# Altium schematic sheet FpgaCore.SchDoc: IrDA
size A4; Organization: Microprocessor-Design Pty Ltd; Address1: 18/110 Caroline Street; Address2: South Yarra; Address3: VIC 3141; Address4: Australia; DocumentNumber: 1; SheetNumber: 1; SheetTotal: 3
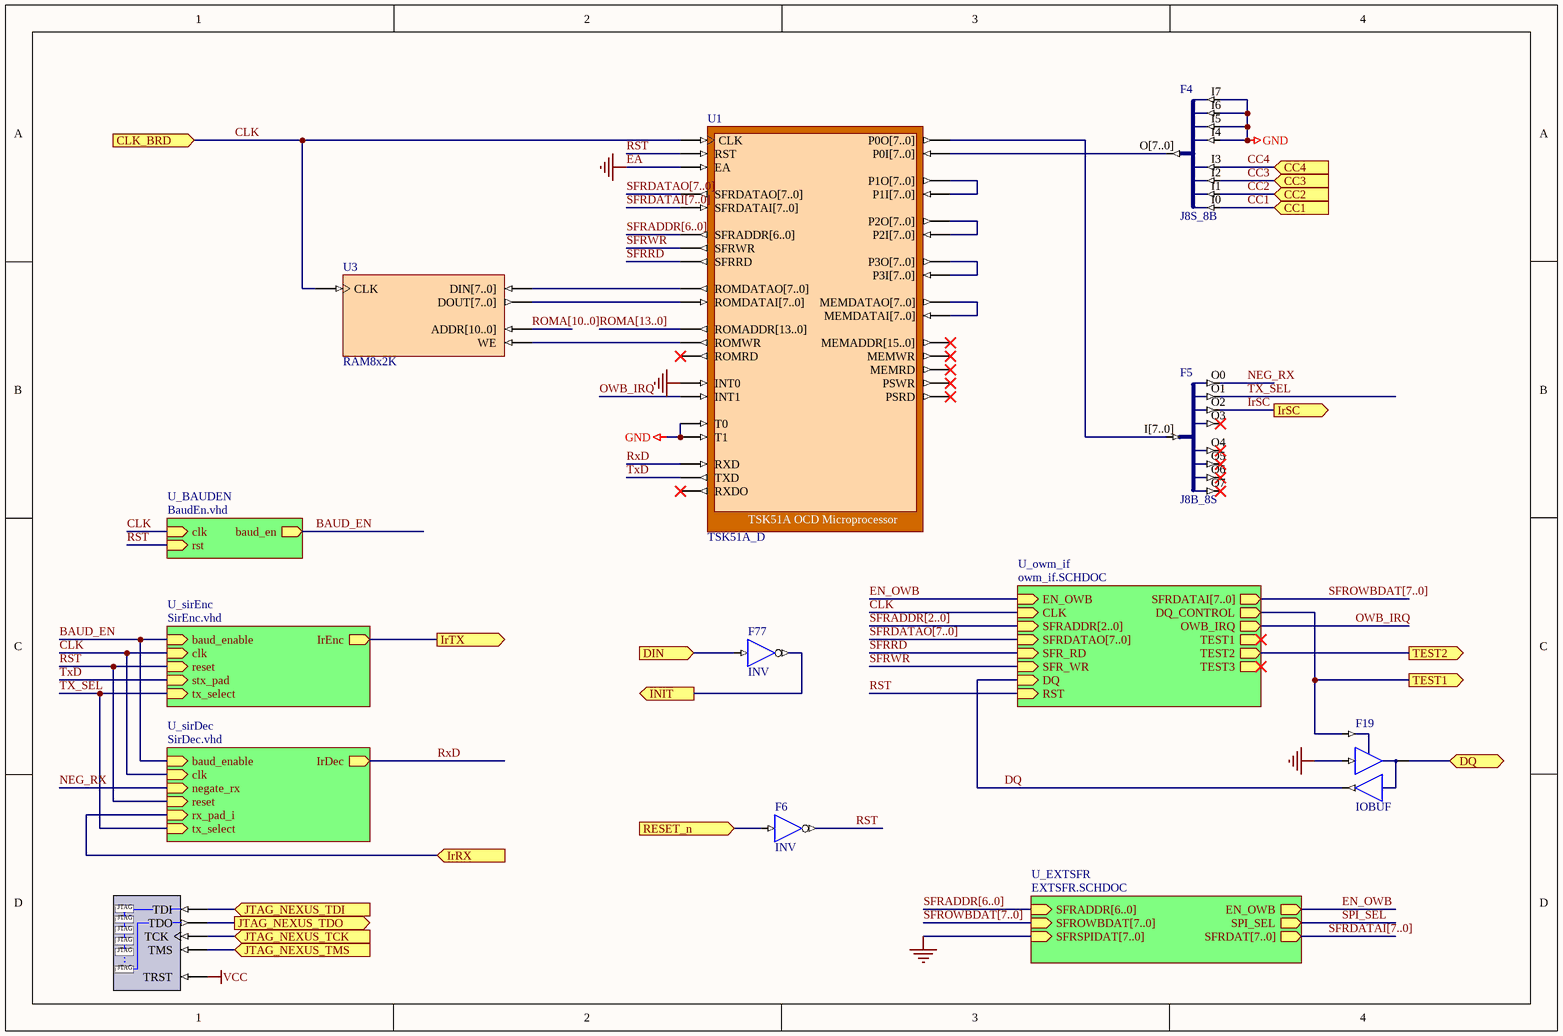
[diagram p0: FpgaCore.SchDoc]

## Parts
F4  J8S_8B
F5  J8B_8S
F6  INV
F19  IOBUF
F77  INV
NEXUS_JTAG_PORT  NEXUS_JTAG_PORT  (value not drawn)
U1  TSK51A_D
U3  RAM8x2K

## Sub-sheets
U_BAUDEN = BaudEn.vhd: baud_en (out), clk (in), rst (in)  | VHDLENTITY: BAUDEN
U_EXTSFR = EXTSFR.SCHDOC: SFRADDR[6..0] (in), EN_OWB (out), SPI_SEL (out), SFROWBDAT[7..0] (in), SFRSPIDAT[7..0] (in), SFRDAT[7..0] (out)
U_owm_if = owm_if.SCHDOC: EN_OWB (in), CLK (in), SFRADDR[2..0] (in), SFRDATAO[7..0] (in), SFRDATAI[7..0] (out), DQ_CONTROL (out), OWB_IRQ (out), SFR_RD (in), SFR_WR (in), DQ (in), RST (in), TEST1 (out), TEST2 (out), TEST3 (out)
U_sirDec = SirDec.vhd: baud_enable (in), clk (in), IrDec (out), negate_rx (in), reset (in), rx_pad_i (in), tx_select (in)  | VHDLENTITY: sirDec
U_sirEnc = SirEnc.vhd: baud_enable (in), clk (in), IrEnc (out), reset (in), stx_pad (in), tx_select (in)  | VHDLENTITY: sirEnc

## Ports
CC1 (in), CC2 (in), CC3 (in), CC4 (in), CLK_BRD (in), DIN (in), DQ (bidir), INIT (out), IrRX (in), IrSC (out), IrTX (out), JTAG_NEXUS_TCK (in), JTAG_NEXUS_TDI (in), JTAG_NEXUS_TDO (out), JTAG_NEXUS_TMS (in), RESET_n (in), TEST1 (out), TEST2 (out)

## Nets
EA: F4.I4 F4.I5 F4.I6 F4.I7 F19.I U1.EA U1.INT0 U1.T0 U1.T1  [also labelled GND]
VCC: NEXUS_JTAG_PORT.TRST
BAUD_EN: sheet U_sirDec/baud_enable, sheet U_sirEnc/baud_enable, sheet U_BAUDEN/baud_en
CC1: F4.I0 ; port CC1
CC2: F4.I1 ; port CC2
CC3: F4.I2 ; port CC3
CC4: F4.I3 ; port CC4
CLK: U1.CLK U3.CLK ; port CLK_BRD, sheet U_sirDec/clk, sheet U_sirEnc/clk, sheet U_BAUDEN/clk, sheet U_owm_if/CLK
DIN: F77.I ; port DIN
DQ: F19.O ; sheet U_owm_if/DQ
DQ: F19.IO ; port DQ  [a separate net that carries the same name]
EN_OWB: sheet U_EXTSFR/EN_OWB, sheet U_owm_if/EN_OWB
INIT: F77.O ; port INIT
IrRX: port IrRX, sheet U_sirDec/rx_pad_i
IrSC: F5.O2 ; port IrSC
IrTX: port IrTX, sheet U_sirEnc/IrEnc
JTAG_NEXUS_TCK: NEXUS_JTAG_PORT.TCK ; port JTAG_NEXUS_TCK
JTAG_NEXUS_TDI: NEXUS_JTAG_PORT.TDI ; port JTAG_NEXUS_TDI
JTAG_NEXUS_TDO: NEXUS_JTAG_PORT.TDO ; port JTAG_NEXUS_TDO
JTAG_NEXUS_TMS: NEXUS_JTAG_PORT.TMS ; port JTAG_NEXUS_TMS
NEG_RX: F5.O0 ; sheet U_sirDec/negate_rx
OWB_IRQ: U1.INT1 ; sheet U_owm_if/OWB_IRQ
RESET_n: F6.I ; port RESET_n
RST: F6.O U1.RST ; sheet U_sirDec/reset, sheet U_sirEnc/reset, sheet U_BAUDEN/rst, sheet U_owm_if/RST
RxD: U1.RXD ; sheet U_sirDec/IrDec
SFRRD: U1.SFRRD ; sheet U_owm_if/SFR_RD
SFRWR: U1.SFRWR ; sheet U_owm_if/SFR_WR
TEST1: F19.T ; port TEST1, sheet U_owm_if/DQ_CONTROL
TEST2: port TEST2, sheet U_owm_if/TEST2
TX_SEL: F5.O1 ; sheet U_sirDec/tx_select, sheet U_sirEnc/tx_select
TxD: U1.TXD ; sheet U_sirEnc/stx_pad
NetU1_ROMWR: U1.ROMWR U3.WE

Not connected (* = marked no-connect by the designer): F4 O[7..0]; F5 I[7..0] O3* O4* O5* O6* O7*; U1 MEMADDR[15..0]* MEMDATAI[7..0] MEMDATAO[7..0] MEMRD* MEMWR* P0I[7..0] P0O[7..0] P1I[7..0] P1O[7..0] P2I[7..0] P2O[7..0] P3I[7..0] P3O[7..0] PSRD* PSWR* ROMADDR[13..0] ROMDATAI[7..0] ROMDATAO[7..0] ROMRD* RXDO* SFRADDR[6..0] SFRDATAI[7..0] SFRDATAO[7..0]; U3 ADDR[10..0] DIN[7..0] DOUT[7..0]

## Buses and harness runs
bus ROMA[10..0]
bus ROMA[13..0]
bus SFRADDR[2..0] = sheet U_owm_if/SFRADDR[2..0]
bus SFRADDR[6..0]
bus SFRADDR[6..0] = sheet U_EXTSFR/SFRADDR[6..0]
bus SFRDATAI[7..0]
bus SFRDATAI[7..0] = sheet U_EXTSFR/SFRDAT[7..0]
bus SFRDATAO[7..0]
bus SFRDATAO[7..0] = sheet U_owm_if/SFRDATAO[7..0]
bus SFROWBDAT[7..0] = sheet U_EXTSFR/SFROWBDAT[7..0]
bus SFROWBDAT[7..0] = sheet U_owm_if/SFRDATAI[7..0]

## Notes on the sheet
- Labels drawn without touching a wire or pin: GNDBUS[..]

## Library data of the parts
F4 = J8S_8B: 8 Single pin inputs to single 8-Bit output bus; ArchiveName: GENERIC
F5 = J8B_8S: 8-Bit input bus to 8 single pin outputs; ArchiveName: GENERIC
F6 F77 = INV: Inverter; ArchiveName: GENERIC
F19 = IOBUF: Input/Output Buffer; ArchiveName: GENERIC
NEXUS_JTAG_PORT = NEXUS_JTAG_PORT: Nexus Processor JTAG Chain Connector; NEXUS_JTAG_CONNECTOR: True
U1 = TSK51A_D: TSK51A OCD Microprocessor; NEXUS_CORE: Processor_OCDS; NEXUS_JTAG_DEVICE: True; NEXUS_JTAG_ORDER: 0; ChildModel1: RAM256x8_TSK51D; ChildCore1: U3; Memory_Configuration: Record[NEXUS_CORE]{}ComponentDesignator[iram]{}Memory_Depth[256]{}Memory_UsageType[ram]{}ProgramDownloadAddress[0x0]{}Memory_BusType[c51:idata_bus]{n}Record[NEXUS_CORE]{}ComponentDesignator[xram]{}Memory_Depth[64k]{}Memory_UsageType[ram]{}ProgramDownloadAddress[0x0]{}Memory_BusType[c51:xdata_bus]{n}Record[NEXUS_CORE]{}ComponentDesignator[xrom]{}Memory_Depth[64k]{}Memory_UsageType[rom]{}ProgramDownloadAddress[0x0]{}Memory_BusType[c51:code_bus]{n}
U3 = RAM8x2K: Single Port Random Access Memory 2048 x 8; Memory_Depth: 2048; Memory_Type: RAM_SinglePortBlock; Memory_Width: 8; Memory_ClockEdge: Rising; Nexus_Core: Memory_Program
